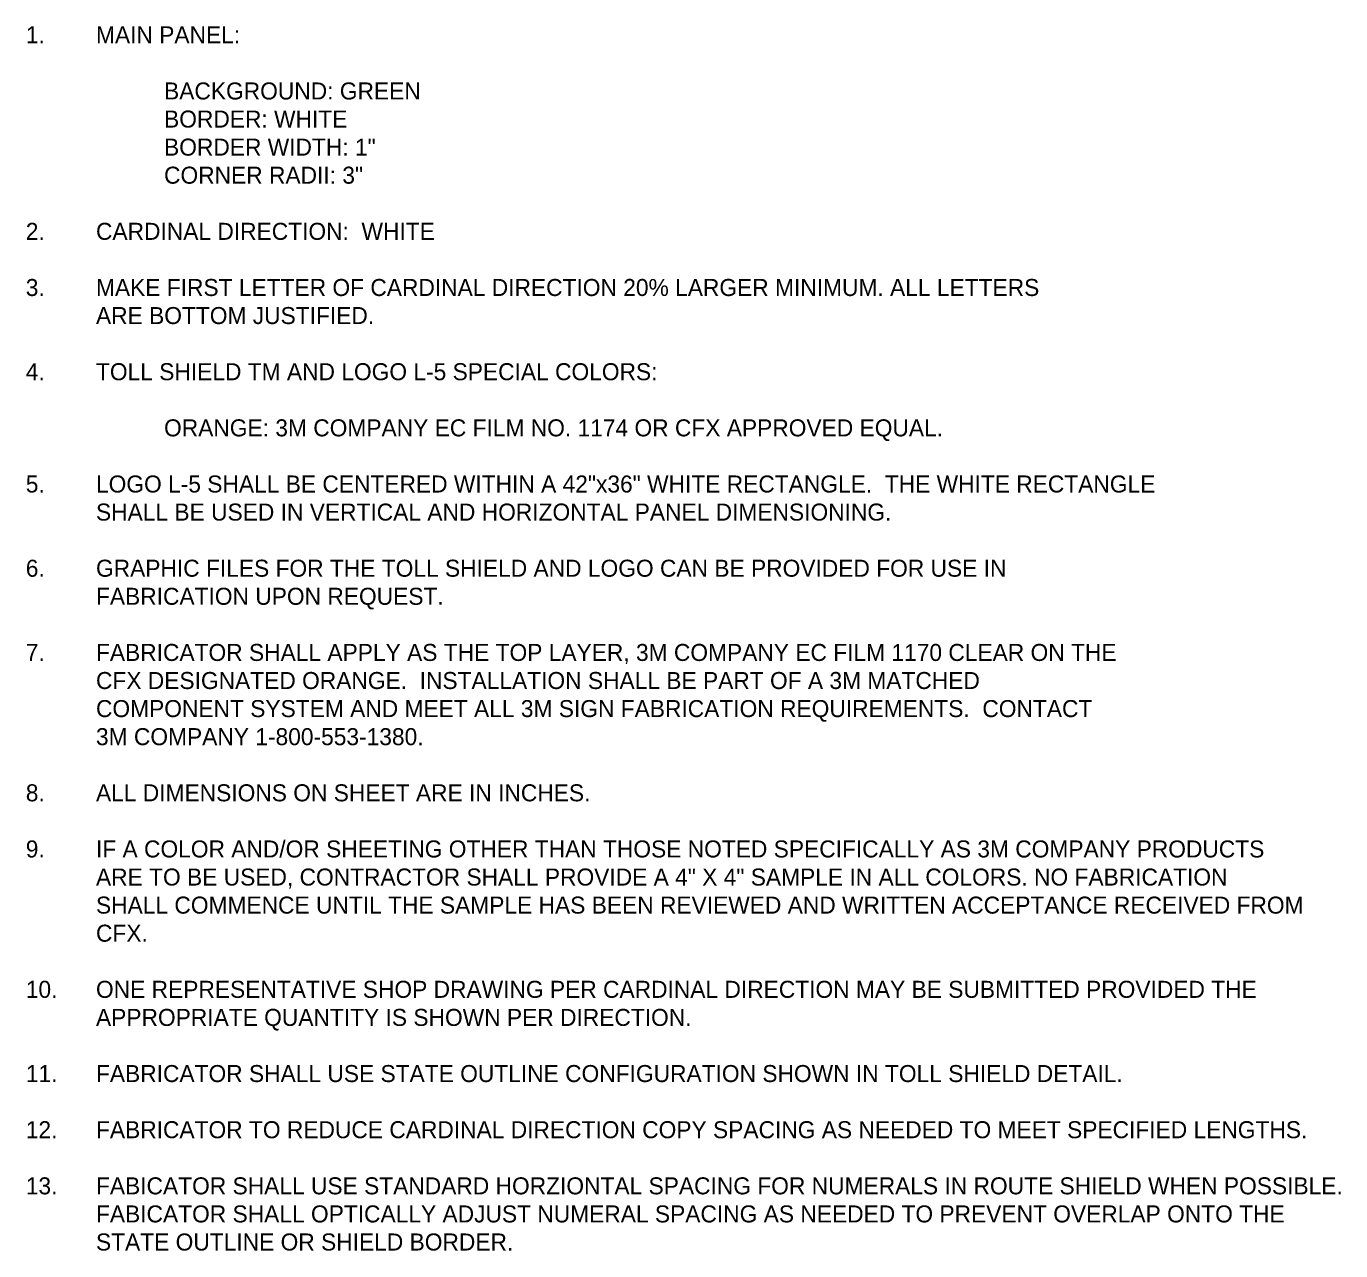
# Model space of a CAD drawing. Extents: x 51788 to 52424, y 9835 to 10249.
# Drawn here: x 52148.8 to 52365.1, y 10047.8 to 10249.3 of the extents above; entities that cross this region are included whole.
import ezdxf

# ---------------------------------------------------------------- set-up
doc = ezdxf.new("R2010")
doc.units = 0
doc.layers.add('TextNotes', color=7, linetype='Continuous')

msp = doc.modelspace()

# ---------------------------------------------------------------- texts
at = {"layer": 'TextNotes'}
for s, p in [('1.', (52148.75, 10246.52)), ('MAIN PANEL:', (52160.3, 10246.52)), ('BACKGROUND: GREEN', (52171.5, 10237.28)), ('BORDER: WHITE', (52171.5, 10232.66)), ('BORDER WIDTH: 1"', (52171.5, 10228.04)), ('CORNER RADII: 3"', (52171.5, 10223.42)), ('2.', (52148.75, 10214.18)), ('CARDINAL DIRECTION:  WHITE', (52160.3, 10214.18)), ('3.', (52148.75, 10204.94)), ('MAKE FIRST LETTER OF CARDINAL DIRECTION 20% LARGER MINIMUM. ALL LETTERS', (52160.3, 10204.94)), ('ARE BOTTOM JUSTIFIED.', (52160.3, 10200.32)), ('4.', (52148.75, 10191.08)), ('TOLL SHIELD TM AND LOGO L-5 SPECIAL COLORS:', (52160.3, 10191.08)), ('ORANGE: 3M COMPANY EC FILM NO. 1174 OR CFX APPROVED EQUAL.', (52171.5, 10181.84)), ('5.', (52148.75, 10172.6)), ('LOGO L-5 SHALL BE CENTERED WITHIN A 42"x36" WHITE RECTANGLE.  THE WHITE RECTANGLE', (52160.3, 10172.6)), ('SHALL BE USED IN VERTICAL AND HORIZONTAL PANEL DIMENSIONING.', (52160.3, 10167.98)), ('6.', (52148.75, 10158.74)), ('GRAPHIC FILES FOR THE TOLL SHIELD AND LOGO CAN BE PROVIDED FOR USE IN', (52160.3, 10158.74)), ('FABRICATION UPON REQUEST.', (52160.3, 10154.12)), ('7.', (52148.75, 10144.88)), ('FABRICATOR SHALL APPLY AS THE TOP LAYER, 3M COMPANY EC FILM 1170 CLEAR ON THE', (52160.3, 10144.88)), ('CFX DESIGNATED ORANGE.  INSTALLATION SHALL BE PART OF A 3M MATCHED', (52160.3, 10140.26)), ('COMPONENT SYSTEM AND MEET ALL 3M SIGN FABRICATION REQUIREMENTS.  CONTACT', (52160.3, 10135.64)), ('3M COMPANY 1-800-553-1380.', (52160.3, 10131.02)), ('8.', (52148.75, 10121.78)), ('ALL DIMENSIONS ON SHEET ARE IN INCHES.', (52160.3, 10121.78)), ('9.', (52148.75, 10112.54)), ('IF A COLOR AND/OR SHEETING OTHER THAN THOSE NOTED SPECIFICALLY AS 3M COMPANY PRODUCTS', (52160.3, 10112.54)), ('ARE TO BE USED, CONTRACTOR SHALL PROVIDE A 4" X 4" SAMPLE IN ALL COLORS. NO FABRICATION', (52160.3, 10107.92)), ('SHALL COMMENCE UNTIL THE SAMPLE HAS BEEN REVIEWED AND WRITTEN ACCEPTANCE RECEIVED FROM ', (52160.3, 10103.3)), ('CFX.', (52160.3, 10098.68)), ('10.', (52148.75, 10089.44)), ('ONE REPRESENTATIVE SHOP DRAWING PER CARDINAL DIRECTION MAY BE SUBMITTED PROVIDED THE', (52160.3, 10089.44)), ('APPROPRIATE QUANTITY IS SHOWN PER DIRECTION.', (52160.3, 10084.82)), ('11.', (52148.75, 10075.58)), ('FABRICATOR SHALL USE STATE OUTLINE CONFIGURATION SHOWN IN TOLL SHIELD DETAIL.', (52160.3, 10075.58)), ('12.', (52148.75, 10066.34)), ('FABRICATOR TO REDUCE CARDINAL DIRECTION COPY SPACING AS NEEDED TO MEET SPECIFIED LENGTHS.', (52160.3, 10066.34)), ('13.', (52148.75, 10057.1)), ('FABICATOR SHALL USE STANDARD HORZIONTAL SPACING FOR NUMERALS IN ROUTE SHIELD WHEN POSSIBLE.', (52160.3, 10057.1)), ('FABICATOR SHALL OPTICALLY ADJUST NUMERAL SPACING AS NEEDED TO PREVENT OVERLAP ONTO THE', (52160.3, 10052.48)), ('STATE OUTLINE OR SHIELD BORDER.', (52160.3, 10047.86))]:
    msp.add_text(s, height=2.8, dxfattribs=at).set_placement(p)

doc.saveas('drawing.dxf')
